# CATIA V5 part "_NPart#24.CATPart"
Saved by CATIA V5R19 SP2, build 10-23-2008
Part number: NES-350(внешн_мод)_1
Definition: design
Nomenclature: NES-350(внешн_мод)
Source: Unknown
Bounding box of the stored display mesh (mm): x -215 to 12, y -115 to 0, z 0 to 50
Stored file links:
  Z:\fausse table rondelle-20220905T211342Z-001\fausse table rondelle\_NPart#24.CATPart
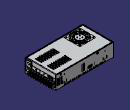
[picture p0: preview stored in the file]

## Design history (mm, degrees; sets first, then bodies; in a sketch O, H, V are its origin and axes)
AxisSystem1: origin (0, 0, 0), X (1, 0, 0), Y (0, 1, 0), Z (0, 0, 1)
Body1 "Тело_0:59" (main body)
  Solid1: solid without history
Body2 "Тело_0:58"
  Solid2: solid without history
Body3 "Тело_0:57"
  Solid3: solid without history
Body4 "Тело_0:56"
  Solid4: solid without history
Body5 "Тело_0:55"
  Solid5: solid without history
Body6 "Тело_0:54"
  Solid6: solid without history
Body7 "Тело_0:53"
  Solid7: solid without history
Body8 "Тело_0:52"
  Solid8: solid without history
Body9 "Тело_0:51"
  Solid9: solid without history
Body10 "Тело_0:50"
  Solid10: solid without history
Body11 "Тело_0:49"
  Solid11: solid without history
Body12 "Тело_0:48"
  Solid12: solid without history
Body13 "Тело_0:47"
  Solid13: solid without history
Body14 "Тело_0:46"
  Solid14: solid without history
Body15 "Тело_0:45"
  Solid15: solid without history
Body16 "Тело_0:44"
  Solid16: solid without history
Body17 "Тело_0:43"
  Solid17: solid without history
Body18 "Тело_0:42"
  Solid18: solid without history
Body19 "Тело_0:41"
  Solid19: solid without history
Body20 "Тело_0:40"
  Solid20: solid without history
Body21 "Тело_0:39"
  Solid21: solid without history
Body22 "Тело_0:38"
  Solid22: solid without history
Body23 "Тело_0:37"
  Solid23: solid without history
Body24 "Тело_0:36"
  Solid24: solid without history
Body25 "Тело_0:35"
  Solid25: solid without history
Body26 "Тело_0:34"
  Solid26: solid without history
Body27 "Тело_0:33"
  Solid27: solid without history
Body28 "Тело_0:32"
  Solid28: solid without history
Body29 "Тело_0:31"
  Solid29: solid without history
Body30 "Тело_0:30"
  Solid30: solid without history
Body31 "Тело_0:29"
  Solid31: solid without history
Body32 "Тело_0:28"
  Solid32: solid without history
Body33 "Тело_0:27"
  Solid33: solid without history
Body34 "Тело_0:26"
  Solid34: solid without history
Body35 "Тело_0:25"
  Solid35: solid without history
Body36 "Тело_0:24"
  Solid36: solid without history
Body37 "Тело_0:23"
  Solid37: solid without history
Body38 "Тело_0:22"
  Solid38: solid without history
Body39 "Тело_0:21"
  Solid39: solid without history
Body40 "Тело_0:20"
  Solid40: solid without history
Body41 "Тело_0:19"
  Solid41: solid without history
Body42 "Тело_0:18"
  Solid42: solid without history
Body43 "Тело_0:17"
  Solid43: solid without history
Body44 "Тело_0:16"
  Solid44: solid without history
Body45 "Тело_0:15"
  Solid45: solid without history
Body46 "Тело_0:14"
  Solid46: solid without history
Body47 "Тело_0:13"
  Solid47: solid without history
Body48 "Тело_0:12"
  Solid48: solid without history
Body49 "Тело_0:11"
  Solid49: solid without history
Body50 "Тело_0:10"
  Solid50: solid without history
Body51 "Тело_0:9"
  Solid51: solid without history
Body52 "Тело_0:8"
  Solid52: solid without history
Body53 "Тело_0:7"
  Solid53: solid without history
Body54 "Тело_0:6"
  Solid54: solid without history
Body55 "Тело_0:5"
  Solid55: solid without history
Body56 "Тело_0:4"
  Solid56: solid without history
Body57 "Тело_0:3"
  Solid57: solid without history
Body58 "Тело_0:2"
  Solid58: solid without history
Body59 "Тело_0:1"
  Solid59: solid without history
